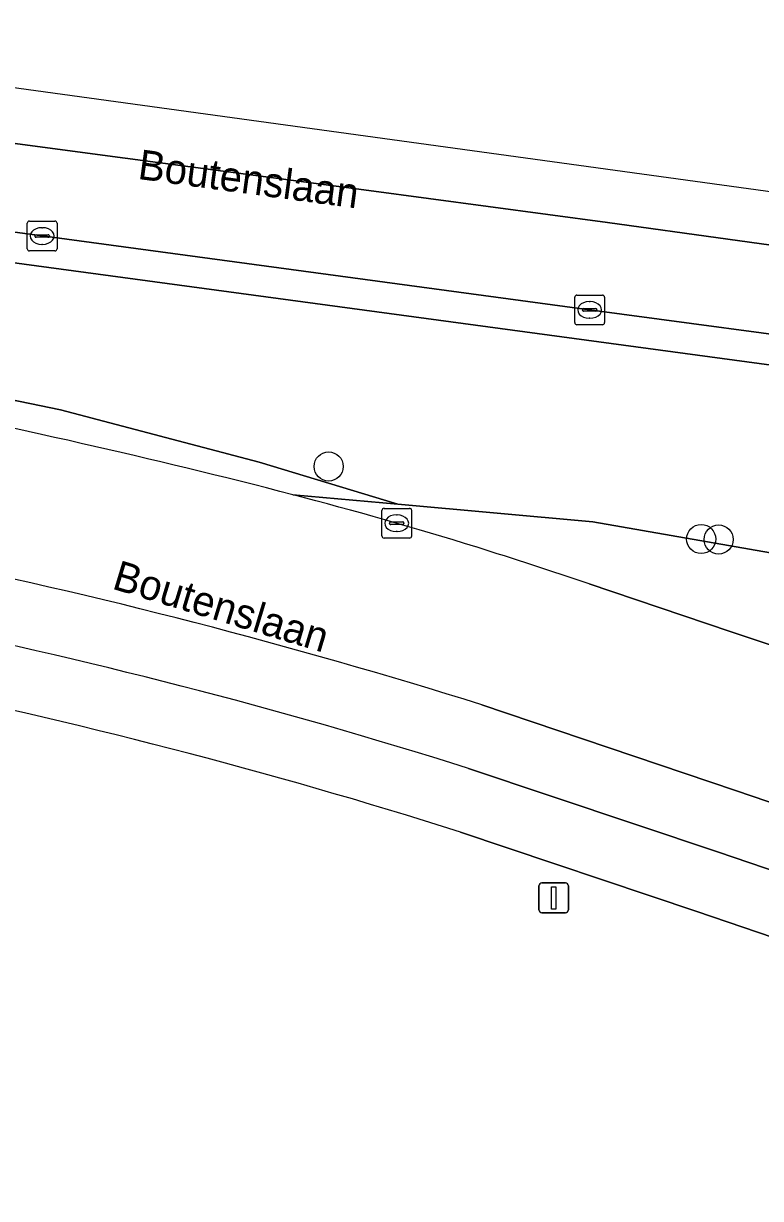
# Model space of a CAD drawing. Extents: x 161258 to 161838, y 380833 to 381727.
# Drawn here: x 161283.02 to 161307.76, y 381686.75 to 381726.19 of the extents above; entities that cross this region are included whole.
import ezdxf

# ---------------------------------------------------------------- set-up
doc = ezdxf.new("R2010")
doc.units = 0
for name, color, linetype in [('IMGEO_Berm_groen', 7, 'Continuous'), ('IMGEO_Boom', 7, 'Continuous'), ('IMGEO_Groenvoorziening', 7, 'Continuous'), ('IMGEO_Kolk', 7, 'Continuous'), ('IMGEO_Lichtmast', 7, 'Continuous'), ('IMGEO_Openbare_ruimte_label', 7, 'Continuous'), ('IMGEO_Parkeervlak_halfverhard', 7, 'Continuous'), ('IMGEO_Rijbaan_lokaal_open', 7, 'Continuous'), ('IMGEO_Rijbaan_regionaal_gesloten', 7, 'Continuous'), ('IMGEO_Voetpad_open', 7, 'Continuous')]:
    doc.layers.add(name, color=color, linetype=linetype)

msp = doc.modelspace()

# ---------------------------------------------------------------- linework, layer by layer
at = {"layer": 'IMGEO_Berm_groen'}
for points in [[(161320.382, 381714.114), (161302.023, 381716.576), (161283.652, 381719.058), (161270.337, 381720.851), (161266.337, 381721.39), (161266.2, 381720.387), (161270.208, 381719.845), (161338.59, 381710.606), (161387.2, 381704.126), (161386.96, 381701.929), (161393.172, 381701.112), (161393.073, 381700.375), (161393.816, 381701.106), (161394.202, 381701.801), (161394.298, 381701.973), (161394.342, 381702.289), (161394.6, 381704.143), (161394.577, 381704.146), (161393.852, 381704.243), (161375.459, 381706.713), (161357.08, 381709.164), (161338.725, 381711.598)], [(161338.59, 381710.606), (161270.208, 381719.845), (161266.2, 381720.387), (161265.65, 381716.362), (161269.693, 381715.83), (161273.11, 381715.38), (161276.343, 381714.86), (161284.269, 381713.225), (161290.931, 381711.459), (161295.591, 381710.053), (161302.129, 381709.465), (161311.935, 381707.75), (161332.472, 381704.88), (161350.111, 381702.164), (161362.451, 381699.429), (161368.695, 381698.551), (161375.302, 381697.96), (161381.143, 381697.835), (161390.776, 381699.021), (161392.132, 381699.449), (161393.073, 381700.375), (161393.172, 381701.112), (161386.96, 381701.929), (161387.2, 381704.126)]]:
    msp.add_lwpolyline(points, close=True, dxfattribs=at)
for points in [[(161284.269, 381713.225), (161276.343, 381714.86), (161273.11, 381715.38), (161269.693, 381715.83), (161265.65, 381716.362), (161265.499, 381715.259), (161273.014, 381714.295), (161273.411, 381714.244), (161275.38, 381713.97), (161276.579, 381713.809), (161277.807, 381713.609)], [(161292.067, 381710.37), (161295.591, 381710.053), (161290.931, 381711.459), (161284.269, 381713.225)], [(161399.097, 381701.337), (161394.298, 381701.973), (161394.202, 381701.801), (161393.816, 381701.106), (161393.073, 381700.375), (161392.132, 381699.449), (161390.776, 381699.021), (161381.143, 381697.835), (161375.302, 381697.96), (161368.695, 381698.551), (161362.451, 381699.429), (161350.111, 381702.164), (161332.472, 381704.88), (161311.935, 381707.75), (161302.129, 381709.465), (161295.591, 381710.053), (161292.067, 381710.37)], [(161302.011, 381707.375), (161306.736, 381705.782), (161314.334, 381703.238), (161374.865, 381682.606), (161389.444, 381677.652), (161389.915, 381679.08), (161390.167, 381679.844), (161391.65, 381679.357), (161392.163, 381679.188)]]:
    msp.add_lwpolyline(points, dxfattribs=at)
for centre, radius, start, end in [((161230.541, 381472.505), 245.694, 75.49771, 78.90835), ((161257.585, 381577.92), 136.865, 72.73355, 75.40769), ((161251.427, 381558.967), 156.792, 71.17851, 72.64015)]:
    msp.add_arc(centre, radius, start, end, dxfattribs=at)
at = {"layer": 'IMGEO_Boom'}
for centre in [(161293.264, 381711.32), (161305.767, 381708.884), (161306.352, 381708.868)]:
    msp.add_circle(centre, 0.489, dxfattribs=at)
at = {"layer": 'IMGEO_Groenvoorziening'}
msp.add_lwpolyline([(161331.864, 381687.437), (161305.615, 381696.385), (161297.687, 381699.047)], dxfattribs=at)
msp.add_arc((161240.768, 381519.494), 188.359, 72.41121, 78.56357, dxfattribs=at)
at = {"layer": 'IMGEO_Kolk'}
for p, q in [((161283.15, 381718.63), (161283.15, 381719.482)), ((161283.225, 381719.556), (161284.077, 381719.556)), ((161284.151, 381719.482), (161284.151, 381718.63)), ((161283.409, 381719.05), (161283.409, 381719.062)), ((161283.847, 381719.013), (161283.449, 381719.013)), ((161283.452, 381719.099), (161283.85, 381719.099)), ((161283.638, 381719.336), (161283.663, 381719.336)), ((161283.893, 381719.062), (161283.893, 381719.05)), ((161283.661, 381718.776), (161283.636, 381718.776)), ((161284.077, 381718.556), (161283.225, 381718.556)), ((161301.597, 381717.075), (161302.449, 381717.075)), ((161301.522, 381716.149), (161301.522, 381717.001)), ((161302.01, 381716.855), (161302.035, 381716.855)), ((161302.523, 381717.001), (161302.523, 381716.149)), ((161301.781, 381716.569), (161301.781, 381716.581)), ((161302.219, 381716.532), (161301.821, 381716.532)), ((161301.824, 381716.618), (161302.222, 381716.618)), ((161302.033, 381716.295), (161302.008, 381716.295)), ((161302.265, 381716.581), (161302.265, 381716.569)), ((161302.449, 381716.075), (161301.597, 381716.075)), ((161295.049, 381708.988), (161295.049, 381709.84)), ((161295.124, 381709.914), (161295.976, 381709.914)), ((161295.537, 381709.694), (161295.562, 381709.694)), ((161296.05, 381709.84), (161296.05, 381708.988)), ((161295.308, 381709.408), (161295.308, 381709.42)), ((161295.746, 381709.371), (161295.348, 381709.371)), ((161295.351, 381709.457), (161295.749, 381709.457)), ((161295.792, 381709.42), (161295.792, 381709.408)), ((161295.976, 381708.914), (161295.124, 381708.914)), ((161295.56, 381709.134), (161295.535, 381709.134))]:
    msp.add_line(p, q, dxfattribs=at)
for points in [[(161283.15, 381718.63), (161283.15, 381719.482)], [(161283.225, 381719.556), (161284.077, 381719.556)], [(161284.151, 381719.482), (161284.151, 381718.63)], [(161284.077, 381718.556), (161283.225, 381718.556)], [(161301.597, 381717.075), (161302.449, 381717.075)], [(161301.522, 381716.149), (161301.522, 381717.001)], [(161302.523, 381717.001), (161302.523, 381716.149)], [(161302.449, 381716.075), (161301.597, 381716.075)], [(161295.049, 381708.988), (161295.049, 381709.84)], [(161295.124, 381709.914), (161295.976, 381709.914)], [(161296.05, 381709.84), (161296.05, 381708.988)], [(161295.976, 381708.914), (161295.124, 381708.914)]]:
    msp.add_lwpolyline(points, dxfattribs=at)
for centre, radius, start, end in [((161283.227, 381719.48), 0.0765, 91.552, 178.448), ((161283.227, 381719.48), 0.0765, 91.552, 178.448), ((161284.075, 381719.48), 0.0765, 1.552, 88.448), ((161284.075, 381719.48), 0.0765, 1.552, 88.448), ((161283.449, 381719.059), 0.0403, 85.8775, 175.7526), ((161283.446, 381719.049), 0.0366, 178.938, 274.7102), ((161283.85, 381719.056), 0.043, 264.8664, 352.4533), ((161283.854, 381719.061), 0.0386, 1.7309, 96.639), ((161283.227, 381718.632), 0.0765, 181.552, 268.448), ((161283.227, 381718.632), 0.0765, 181.552, 268.448), ((161284.075, 381718.632), 0.0765, 271.552, 358.448), ((161284.075, 381718.632), 0.0765, 271.552, 358.448), ((161301.599, 381716.999), 0.0765, 91.552, 178.448), ((161301.599, 381716.999), 0.0765, 91.552, 178.448), ((161302.447, 381716.999), 0.0765, 1.552, 88.448), ((161302.447, 381716.999), 0.0765, 1.552, 88.448), ((161301.821, 381716.578), 0.0403, 85.8775, 175.7526), ((161301.818, 381716.568), 0.0366, 178.938, 274.7102), ((161302.222, 381716.575), 0.043, 264.8664, 352.4533), ((161302.226, 381716.58), 0.0386, 1.7309, 96.639), ((161301.599, 381716.151), 0.0765, 181.552, 268.448), ((161301.599, 381716.151), 0.0765, 181.552, 268.448), ((161302.447, 381716.151), 0.0765, 271.552, 358.448), ((161302.447, 381716.151), 0.0765, 271.552, 358.448), ((161295.126, 381709.838), 0.0765, 91.552, 178.448), ((161295.126, 381709.838), 0.0765, 91.552, 178.448), ((161295.974, 381709.838), 0.0765, 1.552, 88.448), ((161295.974, 381709.838), 0.0765, 1.552, 88.448), ((161295.348, 381709.417), 0.0403, 85.8775, 175.7526), ((161295.345, 381709.407), 0.0366, 178.938, 274.7102), ((161295.749, 381709.414), 0.043, 264.8664, 352.4533), ((161295.753, 381709.419), 0.0386, 1.7309, 96.639), ((161295.126, 381708.99), 0.0765, 181.552, 268.448), ((161295.126, 381708.99), 0.0765, 181.552, 268.448), ((161295.974, 381708.99), 0.0765, 271.552, 358.448), ((161295.974, 381708.99), 0.0765, 271.552, 358.448)]:
    msp.add_arc(centre, radius, start, end, dxfattribs=at)
for centre, major_axis, ratio, start_param, end_param in [((161283.637, 381719.056), (-0.387, 0.002), 0.722429, 4.712389, 7.853982), ((161283.662, 381719.056), (-0.39, 0.002), 0.717154, 1.570796, 4.712389), ((161302.009, 381716.575), (-0.387, 0.002), 0.722429, 4.712389, 7.853982), ((161302.034, 381716.575), (-0.39, 0.002), 0.717154, 1.570796, 4.712389), ((161295.536, 381709.414), (-0.387, 0.002), 0.722429, 4.712389, 7.853982), ((161295.561, 381709.414), (-0.39, 0.002), 0.717154, 1.570796, 4.712389)]:
    msp.add_ellipse(centre, major_axis=major_axis, ratio=ratio, start_param=start_param, end_param=end_param, dxfattribs=at)
at = {"layer": 'IMGEO_Lichtmast'}
for p, q in [((161300.422, 381697.337), (161301.212, 381697.337)), ((161301.212, 381697.337), (161300.422, 381697.337)), ((161300.322, 381696.437), (161300.322, 381697.237)), ((161300.322, 381697.237), (161300.322, 381696.437)), ((161301.312, 381697.237), (161301.312, 381696.437)), ((161301.312, 381696.437), (161301.312, 381697.237)), ((161301.212, 381696.337), (161300.422, 381696.337)), ((161300.422, 381696.337), (161301.212, 381696.337))]:
    msp.add_line(p, q, dxfattribs=at)
msp.add_lwpolyline([(161300.742, 381697.212), (161300.892, 381697.212), (161300.892, 381696.462), (161300.742, 381696.462), (161300.742, 381697.212)], dxfattribs=at)
for centre, start, end in [((161300.422, 381697.237), 90, 180), ((161300.422, 381697.237), 90, 180), ((161301.212, 381697.237), 0, 90), ((161301.212, 381697.237), 360, 90), ((161300.422, 381696.437), 180, 270), ((161300.422, 381696.437), 180, 270), ((161301.212, 381696.437), 270, 0), ((161301.212, 381696.437), 270, 0)]:
    msp.add_arc(centre, 0.1, start, end, dxfattribs=at)
at = {"layer": 'IMGEO_Parkeervlak_halfverhard'}
msp.add_lwpolyline([(161297.963, 381701.183), (161306.347, 381698.37), (161373.055, 381675.655), (161387.563, 381670.711), (161387.916, 381671.748), (161388.263, 381672.768), (161387.854, 381672.902), (161387.182, 381673.123), (161384.929, 381673.889), (161373.728, 381677.698), (161306.917, 381700.444), (161298.406, 381703.319)], dxfattribs=at)
for centre, radius, start, end in [((161239.619, 381515.995), 196.332, 72.57689, 78.43669), ((161242.017, 381524.314), 185.506, 72.4472, 78.64469)]:
    msp.add_arc(centre, radius, start, end, dxfattribs=at)
at = {"layer": 'IMGEO_Rijbaan_lokaal_open'}
msp.add_lwpolyline([(161298.406, 381703.319), (161306.917, 381700.444), (161373.728, 381677.698), (161384.929, 381673.889), (161387.182, 381673.123), (161387.854, 381672.902), (161389.444, 381677.652), (161374.865, 381682.606), (161314.334, 381703.238), (161306.736, 381705.782), (161302.011, 381707.375)], dxfattribs=at)
for centre, radius, start, end in [((161230.541, 381472.505), 245.694, 75.49771, 78.90835), ((161257.585, 381577.92), 136.865, 72.73355, 75.40769), ((161251.427, 381558.967), 156.792, 71.17851, 72.64015), ((161239.619, 381515.995), 196.332, 72.57689, 78.43669)]:
    msp.add_arc(centre, radius, start, end, dxfattribs=at)
at = {"layer": 'IMGEO_Rijbaan_regionaal_gesloten'}
msp.add_lwpolyline([(161395.21, 381708.555), (161266.992, 381726.19), (161266.848, 381725.137), (161266.739, 381724.334), (161270.713, 381723.786), (161274.594, 381723.251), (161286.434, 381721.67), (161294.615, 381720.579), (161302.624, 381719.51), (161314.74, 381717.835), (161322.659, 381716.784), (161334.727, 381715.159), (161346.792, 381713.518), (161358.971, 381711.918), (161371.094, 381710.27), (161383.043, 381708.695), (161395.013, 381707.117)], close=True, dxfattribs=at)
msp.add_lwpolyline([(161383.043, 381708.695), (161371.094, 381710.27), (161358.971, 381711.918), (161346.792, 381713.518), (161334.727, 381715.159), (161322.659, 381716.784), (161314.74, 381717.835), (161302.624, 381719.51), (161294.615, 381720.579), (161286.434, 381721.67), (161274.594, 381723.251), (161270.713, 381723.786), (161266.739, 381724.334), (161266.697, 381724.029), (161266.337, 381721.39), (161270.337, 381720.851), (161283.652, 381719.058), (161302.023, 381716.576), (161320.382, 381714.114), (161338.725, 381711.598), (161357.08, 381709.164), (161375.459, 381706.713), (161393.852, 381704.243)], dxfattribs=at)
at = {"layer": 'IMGEO_Voetpad_open'}
for points in [[(161306.347, 381698.37), (161297.963, 381701.183)], [(161297.687, 381699.047), (161305.615, 381696.385), (161331.864, 381687.437), (161334.877, 381686.353), (161386.886, 381668.72), (161386.954, 381668.921), (161387.563, 381670.711), (161373.055, 381675.655), (161306.347, 381698.37)]]:
    msp.add_lwpolyline(points, dxfattribs=at)
for centre, radius, start, end in [((161242.017, 381524.314), 185.506, 72.4472, 78.64469), ((161240.768, 381519.494), 188.359, 72.41121, 78.56357)]:
    msp.add_arc(centre, radius, start, end, dxfattribs=at)

# ---------------------------------------------------------------- texts
at = {"layer": 'IMGEO_Openbare_ruimte_label'}
for rotation, p in [(352.2993, (161286.832, 381720.976)), (343.1416, (161285.959, 381707.226))]:
    msp.add_text('Boutenslaan', height=1, rotation=rotation, dxfattribs=at).set_placement(p)

doc.saveas('drawing.dxf')
